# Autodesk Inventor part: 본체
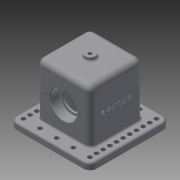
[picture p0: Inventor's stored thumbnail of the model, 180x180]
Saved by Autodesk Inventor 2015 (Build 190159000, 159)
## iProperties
Created: 2018-11
Part Number: 본체
Material: 일반
Document SubType Name: Modeling
Designer: now333
Density: 1 g/cm^3
Appearance: 기본값
Author: now333
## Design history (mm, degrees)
sketch "스케치1"
  geometry: L1 (60, -60)-(-60, -60); L2 (-60, -60)-(-60, 60); L3 (-60, 60)-(60, 60); L4 (60, 60)-(60, -60); L5 (60, -60)-(-60, 60); L6 (-60, -60)-(60, 60); 1 further point
  constraints: 12 end point, 2 midpoint, 2 parallel, 1 horizontal, 1 perpendicular
  dimensions: "d0" = 120 distance of L1.start L1.end; "d1" = 120 distance of L3.end L1.start
extrude "돌출1" new body sketch "스케치1" distance "d2" = 10; taper "d3" = 0 deg
sketch "스케치2"
  geometry: L1 (40, -40)-(-40, -40); L2 (-40, -40)-(-40, 40); L3 (-40, 40)-(40, 40); L4 (40, 40)-(40, -40); L5 (40, -40)-(-40, 40); L6 (-40, -40)-(40, 40); 1 further point
  constraints: 12 end point, 2 midpoint, 2 parallel, 1 horizontal, 1 perpendicular
  dimensions: "d4" = 80 distance of L1.start L1.end; "d5" = 80 distance of L3.end L1.start
extrude "돌출2" join sketch "스케치2" distance "d6" = 80; taper "d7" = 0 deg
sketch "스케치4"
  geometry: L1 (30, 23)-(-30, 23); L2 (-30, 23)-(-30, -23); L3 (-30, -23)-(30, -23); L4 (30, -23)-(30, 23); L5 (30, 23)-(-30, -23); L6 (-30, 23)-(30, -23); 1 further point
  constraints: 12 end point, 2 midpoint, 2 parallel, 1 horizontal, 1 perpendicular
  dimensions: "d8" = 60 distance of L2.end L3.end; "d9" = 46 distance of L1.end L2.end
extrude "돌출3" cut sketch "스케치4" distance "d10" = 80; taper "d11" = 0 deg
sketch "스케치5"
  geometry: C1 r 7.5 at (0, 0); 1 further point
  constraints: 1 centre point, 1 coincident
  dimensions: "d12" = 15 diameter of C1
extrude "돌출4" join sketch "스케치5" distance "d13" = 5; taper "d14" = 0 deg
sketch "스케치6"
  geometry: C1 r 7.5 at (0, 0) reference
hole "구멍1" sketch "스케치6" at (0, 0) diameter "d15" = 4.917; stored, may be unused: countersink angle "d19" = 90 deg, drill point angle "d21" = 118 deg; dims "d16" = 20, "d17" = 4, "d18" = 2, "d20" = 17.1
sketch "스케치7"
  geometry: C1 r 20 at (40, 38); 1 further point
  constraints: 1 centre point, 1 vertical alignment
  dimensions: "d22" = 40 diameter of C1; "d23" = 48 distance of point (40, -10) C1.centre
extrude "돌출5" cut sketch "스케치7" distance "d24" = 14; taper "d25" = 0 deg
sketch "스케치8"
  geometry: L1 (60, -38)-(60, -48) reference; L2 (60, -48)-(-60, -48) reference; L3 (-60, -48)-(-60, -38) reference; L4 (-60, -38)-(-40, -38) reference; L5 (-40, -38)-(-40, 42) reference; L6 (-40, 42)-(40, 42) reference; L7 (40, 42)-(40, -38) reference; L8 (40, -38)-(60, -38) reference; C1 r 20 at (0, 0) reference; C2 r 16.5 at (0, 0); 1 further point
  constraints: 1 centre point, 1 coincident
  dimensions: "d26" = 33 diameter of C2
extrude "돌출6" cut sketch "스케치8" distance "d27" = 3; taper "d28" = 0 deg
sketch "스케치9"
  geometry: C1 r 20 at (40, 38) reference; 2 further points
  constraints: 1 vertical alignment
  dimensions: "d29" = 26 distance of C1.centre point (40, 64)
hole "구멍2" sketch "스케치9" at (40, 64) diameter "d30" = 3.242; stored, may be unused: countersink angle "d34" = 90 deg, drill point angle "d36" = 118 deg; dims "d31" = 8, "d32" = 4, "d33" = 2, "d35" = 10
fillet "모깎기1" dims "d41" = 10
sketch "스케치16"
  geometry: C1 r 3.3 at (-50, -50); A1 r 10 centre (-50, -50) between (-60, -50) and (-50, -60) reference; 1 further point
  constraints: 1 centre point, 1 coincident
  dimensions: "d64" = 6.6 diameter of C1
extrude "돌출8" cut sketch "스케치16" stored distance "d65" = 3; taper "d66" = 0 deg
sketch "스케치18"
  geometry: 2 further points
  constraints: 1 horizontal alignment, 1 other
  dimensions: "d73" = 48 distance of point (10, 40) point (-38, 40)
feature "엠보싱1" sketch "스케치18" dims "d0" = 120, "d1" = 120, "d8" = 60, "d9" = 46, "d74" = 0.5, "d75" = 0
fillet "모깎기2" dims "d76" = 8
fillet "모깎기3" dims "d77" = 3
fillet "모깎기4" dims "d78" = 3
fillet "모깎기5" dims "d79" = 3
chamfer "모따기1" distance "d80" = 1; stored, may be unused: second distance "d81" = 2, angle "d82" = 45 deg
fillet "모깎기6" dims "d83" = 0.6
node "솔리드1"
mirror "대칭1"
pattern_circular "원형 패턴1" dims angle "d38" = 360 deg
mirror "대칭2"
pattern_linear "직사각형 패턴2" dims "d69" = 25
pattern_linear "직사각형 패턴3" dims "d72" = 10
mirror "대칭4"
mirror "대칭5"
node "절단 모서리 투영1"
